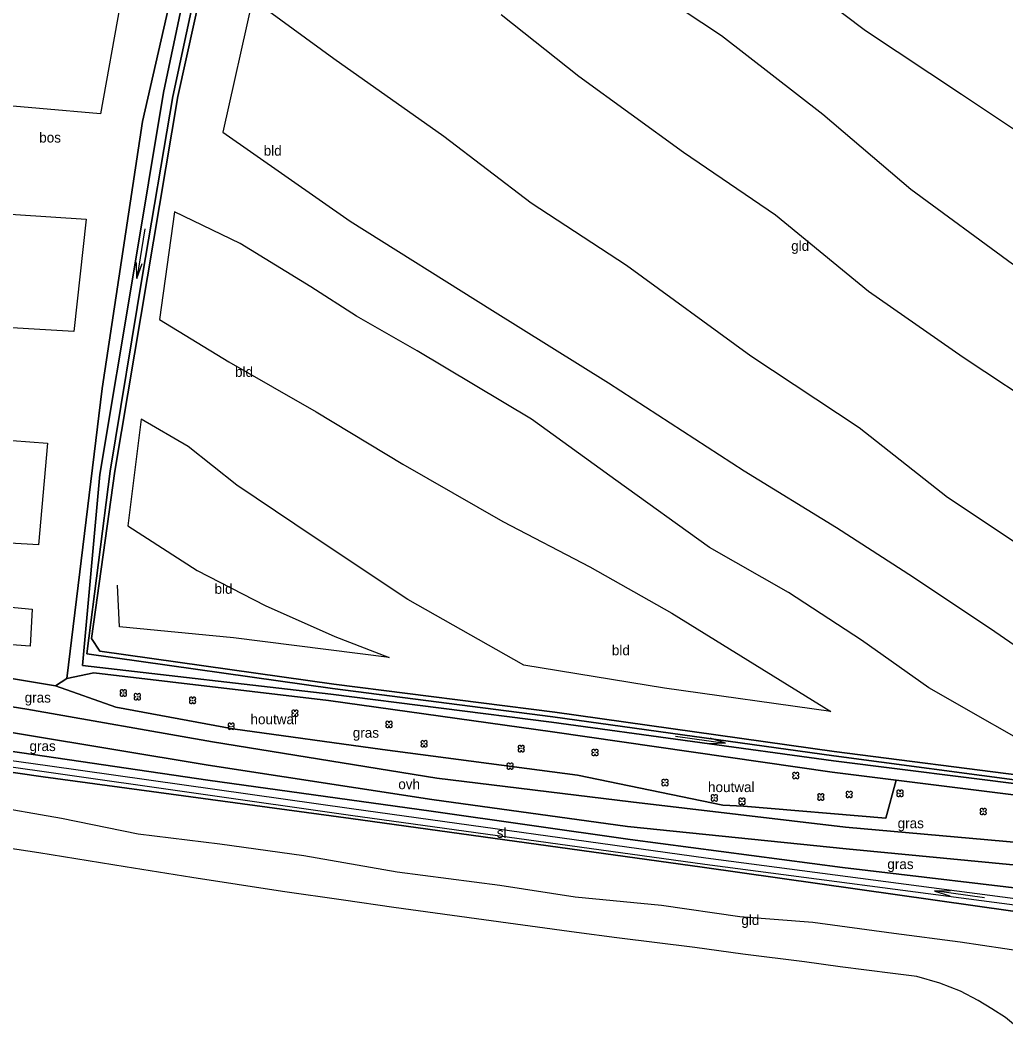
# Model space of a CAD drawing. Extents: x 154825 to 158680, y 370717 to 378075.
# Drawn here: x 155799.6 to 155897.3, y 376810.3 to 376911 of the extents above; entities that cross this region are included whole.
import ezdxf

# ---------------------------------------------------------------- set-up
doc = ezdxf.new("R2010")
doc.units = 0
for name, color, linetype in [('boom', 7, 'Continuous'), ('bos(vs)', 7, 'Continuous'), ('bouwland_akkerland(vs)', 7, 'Continuous'), ('cultuurscheiding', 7, 'Continuous'), ('grasland_productiegrasl(vs)', 7, 'Continuous'), ('grazige vegetatie(vs)', 7, 'Continuous'), ('hoogteverschillijn', 7, 'Continuous'), ('houtwal(vs)', 7, 'Continuous'), ('insteek sloot', 7, 'Continuous'), ('maaiveldlijn algemeen - onverhard', 7, 'Continuous'), ('onverhard(vs)', 7, 'Continuous'), ('Sloot bodem', 7, 'Continuous'), ('sloot(vs)', 7, 'Continuous'), ('stroomrichting  watergangen', 7, 'Continuous'), ('vlak_akkerland', 7, 'Continuous'), ('vlak_Bos', 7, 'Continuous'), ('vlak_Grasland', 7, 'Continuous'), ('vlak_Grazige_vegetatie', 7, 'Continuous')]:
    doc.layers.add(name, color=color, linetype=linetype)

msp = doc.modelspace()

# ---------------------------------------------------------------- linework, layer by layer
at = {"layer": 'boom'}
for centre in [(155809.83, 376844.31), (155811.22, 376843.93), (155816.7, 376843.58), (155826.83, 376842.3), (155820.51, 376841), (155836.16, 376841.19), (155839.63, 376839.27), (155849.26, 376838.79), (155856.58, 376838.4), (155848.16, 376837.06), (155876.48, 376836.12), (155863.52, 376835.43), (155868.4, 376833.91), (155871.14, 376833.57), (155878.96, 376834), (155881.77, 376834.25), (155886.81, 376834.36), (155895.06, 376832.55)]:
    msp.add_circle(centre, 0.006, dxfattribs=at)
for centre, start, end in [((155809.67, 376844.47), 357.075, 272.925), ((155809.99, 376844.47), 267.075, 182.925), ((155809.67, 376844.15), 87.075, 2.925), ((155809.99, 376844.15), 177.075, 92.925), ((155811.06, 376844.09), 357.075, 272.925), ((155811.06, 376843.77), 87.075, 2.925), ((155811.38, 376844.09), 267.075, 182.925), ((155811.38, 376843.77), 177.075, 92.925), ((155816.54, 376843.74), 357.075, 272.925), ((155816.54, 376843.42), 87.075, 2.925), ((155816.85, 376843.74), 267.075, 182.925), ((155816.85, 376843.42), 177.075, 92.925), ((155826.68, 376842.46), 357.075, 272.925), ((155826.99, 376842.46), 267.075, 182.925), ((155826.68, 376842.14), 87.075, 2.925), ((155826.99, 376842.14), 177.075, 92.925), ((155836, 376841.35), 357.075, 272.925), ((155836.32, 376841.35), 267.075, 182.925), ((155820.36, 376841.16), 357.075, 272.925), ((155820.36, 376840.85), 87.075, 2.925), ((155820.67, 376841.16), 267.075, 182.925), ((155820.67, 376840.85), 177.075, 92.925), ((155836, 376841.03), 87.075, 2.925), ((155836.32, 376841.03), 177.075, 92.925), ((155839.48, 376839.43), 357.075, 272.925), ((155839.79, 376839.43), 267.075, 182.925), ((155839.48, 376839.11), 87.075, 2.925), ((155839.79, 376839.11), 177.075, 92.925), ((155849.11, 376838.95), 357.075, 272.925), ((155849.11, 376838.63), 87.075, 2.925), ((155849.42, 376838.95), 267.075, 182.925), ((155849.42, 376838.63), 177.075, 92.925), ((155856.42, 376838.56), 357.075, 272.925), ((155856.73, 376838.56), 267.075, 182.925), ((155856.42, 376838.25), 87.075, 2.925), ((155856.73, 376838.25), 177.075, 92.925), ((155848, 376837.21), 357.075, 272.925), ((155848, 376836.9), 87.075, 2.925), ((155848.32, 376837.21), 267.075, 182.925), ((155848.32, 376836.9), 177.075, 92.925), ((155863.36, 376835.59), 357.075, 272.925), ((155863.67, 376835.59), 267.075, 182.925), ((155876.32, 376836.28), 357.075, 272.925), ((155876.32, 376835.96), 87.075, 2.925), ((155876.64, 376836.28), 267.075, 182.925), ((155876.64, 376835.96), 177.075, 92.925), ((155863.36, 376835.27), 87.075, 2.925), ((155863.67, 376835.27), 177.075, 92.925), ((155881.61, 376834.4), 357.075, 272.925), ((155881.93, 376834.4), 267.075, 182.925), ((155886.65, 376834.52), 357.075, 272.925), ((155886.97, 376834.52), 267.075, 182.925), ((155868.24, 376834.07), 357.075, 272.925), ((155868.24, 376833.75), 87.075, 2.925), ((155868.56, 376834.07), 267.075, 182.925), ((155868.56, 376833.75), 177.075, 92.925), ((155870.99, 376833.73), 357.075, 272.925), ((155870.99, 376833.41), 87.075, 2.925), ((155871.3, 376833.73), 267.075, 182.925), ((155871.3, 376833.41), 177.075, 92.925), ((155878.8, 376834.16), 357.075, 272.925), ((155878.8, 376833.84), 87.075, 2.925), ((155879.12, 376834.16), 267.075, 182.925), ((155879.12, 376833.84), 177.075, 92.925), ((155881.61, 376834.09), 87.075, 2.925), ((155881.93, 376834.09), 177.075, 92.925), ((155886.65, 376834.2), 87.075, 2.925), ((155886.97, 376834.2), 177.075, 92.925), ((155894.9, 376832.71), 357.075, 272.925), ((155894.9, 376832.4), 87.075, 2.925), ((155895.21, 376832.71), 267.075, 182.925), ((155895.21, 376832.4), 177.075, 92.925)]:
    msp.add_arc(centre, 0.158, start, end, dxfattribs=at)
at = {"layer": 'bos(vs)'}
msp.add_lwpolyline([(155707.98, 376936.31), (155709.06, 376926.66), (155710.19, 376916.09), (155711.3, 376903.83), (155707.93, 376894.26), (155707.32, 376891.22), (155709.05, 376884.55), (155711.14, 376878.22), (155715.14, 376871.74), (155721.77, 376865.05), (155731.05, 376858.48), (155738.77, 376855.49), (155749.59, 376852.93), (155762.49, 376851.8), (155803.11, 376845.02)], dxfattribs=at)
at = {"layer": 'cultuurscheiding'}
msp.add_lwpolyline([(155804.24, 376845.73), (155803.11, 376845.02)], dxfattribs=at)
at = {"layer": 'hoogteverschillijn'}
for points in [[(155874.66, 376916.61), (155883.38, 376909.98), (155892.9, 376903.67), (155900.14, 376898.84), (155908.78, 376893.81), (155916.88, 376889.16), (155924.11, 376884.74), (155933.83, 376879.1), (155929.3, 376866.27), (155918.02, 376873.64), (155908.49, 376879.84), (155897.95, 376886.83), (155887.87, 376894.23), (155879.15, 376901.66), (155869.11, 376909.47), (155861.42, 376914.58)], [(155901.98, 376856.72), (155891.51, 376863.7), (155882.76, 376870.61), (155872.03, 376877.7), (155859.69, 376886.7), (155850.25, 376892.86), (155841.61, 376899.48), (155830.7, 376907.17), (155822.64, 376913.11), (155819.68, 376899.92), (155832.3, 376891.07), (155846.42, 376882.22), (155857.91, 376875.04), (155871.35, 376866.32), (155880.5, 376860.73), (155888.13, 376855.79), (155896.2, 376850.4), (155902.14, 376846.3)], [(155809.5, 376912.57), (155807.56, 376901.73), (155795.44, 376902.79)], [(155847.28, 376911.58), (155854.99, 376905.45), (155865.34, 376897.94), (155874.47, 376891.7), (155883.67, 376884.14), (155893.08, 376877.6), (155901.55, 376871.98)], [(155792.6, 376892.19), (155806.16, 376891.28), (155804.92, 376880.15), (155795.39, 376880.7)], [(155902.52, 376837.48), (155889.68, 376844.82), (155882.99, 376849.55), (155875.74, 376854.28), (155867.94, 376858.73), (155858.63, 376865.41), (155850.29, 376871.45), (155838.96, 376878.23), (155832.94, 376881.67), (155828.41, 376884.57), (155821.42, 376888.86), (155814.89, 376892.02), (155813.41, 376881.34), (155820.29, 376877.15), (155828.94, 376872.18), (155837.53, 376866.99), (155847.44, 376861.3), (155856.07, 376856.81), (155864.19, 376852.23), (155879.95, 376842.48), (155863.48, 376844.78), (155849.52, 376847.08), (155838.02, 376853.57), (155828.74, 376859.74), (155821.08, 376864.91), (155816.24, 376868.75), (155811.58, 376871.45), (155810.27, 376860.87), (155817.16, 376856.45), (155823.89, 376852.98), (155830.8, 376849.9), (155836.17, 376847.82), (155820.74, 376849.77), (155809.46, 376850.87), (155809.25, 376854.98)], [(155793.52, 376869.72), (155802.32, 376869.07), (155801.42, 376858.99), (155789.45, 376859.68)], [(155793.41, 376853.32), (155800.78, 376852.61), (155800.6, 376848.94), (155785.32, 376850.07)], [(155796.09, 376833.21), (155803.71, 376831.9), (155811.31, 376830.35), (155819.39, 376829.36), (155827.73, 376828.18), (155836.97, 376826.58), (155847.15, 376825.24), (155854.61, 376824.11), (155863.16, 376823.27), (155870.92, 376822.14), (155878.16, 376821.57), (155886.21, 376820.5), (155892.77, 376819.62), (155901.63, 376818.3)], [(155899.45, 376810.33), (155897.26, 376812.15), (155895.92, 376813), (155894.54, 376813.82), (155892.79, 376814.76), (155890.75, 376815.55), (155888.48, 376816.21), (155886.08, 376816.49), (155880.88, 376817.16), (155877.34, 376817.64), (155871.24, 376818.42), (155866.47, 376819.06), (155858.73, 376820.04), (155854.73, 376820.55), (155844.83, 376821.9), (155836.65, 376823.05), (155831.64, 376823.75), (155825.59, 376824.62), (155816.62, 376826), (155810.02, 376827.08), (155801.47, 376828.46), (155795.3, 376829.39)]]:
    msp.add_lwpolyline(points, dxfattribs=at)
at = {"layer": 'houtwal(vs)'}
msp.add_lwpolyline([(155803.11, 376845.02), (155809.07, 376842.91), (155820.67, 376840.76), (155835.5, 376838.71), (155854.84, 376836.17), (155869.25, 376833.19), (155871.29, 376833.07), (155885.39, 376831.91), (155886.44, 376835.67)], dxfattribs=at)
at = {"layer": 'insteek sloot'}
for points in [[(155951.48, 376912.04), (155950.81, 376910.1), (155944.24, 376887.93), (155932.69, 376850.87), (155927.1, 376832.28), (155925.6, 376832.14), (155908.83, 376834.69), (155899.86, 376836), (155880.29, 376838.49), (155852.58, 376842.4), (155830.69, 376845.17), (155807.49, 376848.44), (155806.69, 376849.7), (155808.97, 376866.3), (155812.21, 376885.55), (155815.22, 376903.44), (155820.87, 376929.02), (155827.55, 376949.9), (155825.68, 376950.6)], [(155710.74, 376938.93), (155711.93, 376937.32), (155749.4, 376933.71), (155779.55, 376931.02), (155798.58, 376929.34), (155817.7, 376927.17), (155811.74, 376900.95), (155807.72, 376874.51), (155804.24, 376845.73)], [(155804.24, 376845.73), (155806.9, 376846.29), (155830.15, 376843.55), (155852.38, 376840.45), (155880.09, 376836.47), (155886.44, 376835.67), (155900.16, 376833.93), (155910.13, 376832.74), (155924.43, 376829.92), (155927.16, 376829.71), (155928.35, 376830.7), (155929.48, 376833.95), (155934.43, 376850.63), (155938.1, 376861.47), (155945.95, 376887.57), (155952.86, 376909.7), (155953.45, 376911.73), (155952.69, 376912.04), (155951.48, 376912.04)], [(155917.26, 376821.97), (155902.89, 376824.44), (155881.12, 376826.99), (155860.07, 376829.77), (155840.33, 376832.6), (155818.19, 376835.66), (155799.77, 376838.37), (155777.89, 376841.55)], [(155917.26, 376821.97), (155917.56, 376821.1), (155917.38, 376820.35), (155916.96, 376819.99), (155897.99, 376822.69), (155867.21, 376827.04), (155832.39, 376831.87), (155801.87, 376835.98), (155784.26, 376838.54)]]:
    msp.add_lwpolyline(points, dxfattribs=at)
at = {"layer": 'maaiveldlijn algemeen - onverhard'}
for points in [[(155761.97, 376849), (155778.08, 376846.25), (155800.28, 376842.69), (155818.67, 376839.48), (155840.9, 376835.86), (155860.13, 376833.5), (155881.4, 376830.99), (155903.31, 376829.04), (155916.93, 376827.42), (155923.18, 376826.59), (155927.44, 376827.44), (155929.98, 376827.65)], [(155927.76, 376819.58), (155925.74, 376822.59), (155921.05, 376823.98), (155916.67, 376825.04), (155903.18, 376826.77), (155881.48, 376828.86), (155859.8, 376831.07), (155840.39, 376833.74), (155818.23, 376837.16), (155799.73, 376840.22), (155778.26, 376843.76), (155761.03, 376845.99)]]:
    msp.add_lwpolyline(points, dxfattribs=at)
at = {"layer": 'Sloot bodem'}
for points in [[(155952.92, 376911.73), (155945.45, 376887.82), (155933.51, 376850.77), (155927.84, 376832.29), (155926.8, 376831.25), (155925.43, 376831.34), (155909.7, 376833.81), (155899.67, 376835.15), (155880.2, 376837.58), (155852.26, 376841.4), (155830.4, 376844.19), (155805.78, 376847.03), (155807.51, 376865.98), (155810.82, 376885.92), (155813.8, 376903.84), (155819.14, 376929.12)], [(155820.25, 376929.18), (155814.74, 376903.44), (155811.72, 376885.72), (155808.51, 376866.3), (155806.2, 376848.2), (155830.56, 376844.76), (155852.39, 376841.94), (155880.24, 376838.08), (155899.63, 376835.5), (155909.79, 376834.4), (155925.47, 376831.94), (155926.84, 376831.85), (155927.27, 376832.47), (155932.94, 376850.95), (155944.87, 376888), (155952.35, 376911.91)], [(155784.16, 376839.02), (155802.22, 376836.49), (155832.36, 376832.21), (155867.47, 376827.34), (155898.15, 376823.29), (155917.01, 376820.38), (155917.1, 376820.97), (155898.22, 376823.89), (155867.56, 376827.93), (155832.44, 376832.81), (155802.3, 376837.09), (155784.24, 376839.61)]]:
    msp.add_lwpolyline(points, dxfattribs=at)
at = {"layer": 'stroomrichting  watergangen'}
for p, q in [((155811.95, 376890.32), (155811.16, 376885.39)), ((155811.16, 376885.39), (155811.13, 376886.97)), ((155811.17, 376885.41), (155811.69, 376886.9)), ((155864.57, 376840.01), (155869.52, 376839.33)), ((155869.5, 376839.34), (155868, 376839.83)), ((155869.52, 376839.33), (155867.94, 376839.27)), ((155890.24, 376824.68), (155891.81, 376824.74)), ((155895.18, 376824), (155890.24, 376824.68)), ((155890.25, 376824.66), (155891.75, 376824.18))]:
    msp.add_line(p, q, dxfattribs=at)
at = {"layer": 'vlak_akkerland'}
msp.add_lwpolyline([(155951.48, 376912.04), (155950.81, 376910.1), (155944.24, 376887.93), (155932.69, 376850.87), (155927.1, 376832.28), (155925.6, 376832.14), (155908.83, 376834.69), (155899.86, 376836), (155880.29, 376838.49), (155852.58, 376842.4), (155830.69, 376845.17), (155807.49, 376848.44), (155806.69, 376849.7), (155808.97, 376866.3), (155812.21, 376885.55), (155815.22, 376903.44), (155820.87, 376929.02)], dxfattribs=at)
at = {"layer": 'vlak_Bos'}
msp.add_lwpolyline([(155804.24, 376845.73), (155803.11, 376845.02), (155762.49, 376851.8), (155749.59, 376852.93), (155738.77, 376855.49), (155731.05, 376858.48), (155721.77, 376865.05), (155715.14, 376871.74), (155711.14, 376878.22), (155709.05, 376884.55), (155707.32, 376891.22), (155707.93, 376894.26), (155711.3, 376903.83), (155710.19, 376916.09), (155709.06, 376926.66), (155707.98, 376936.31), (155710.74, 376938.93), (155711.93, 376937.32), (155749.4, 376933.71), (155779.55, 376931.02), (155798.58, 376929.34), (155817.7, 376927.17), (155811.74, 376900.95), (155807.72, 376874.51)], close=True, dxfattribs=at)
at = {"layer": 'vlak_Grasland'}
for points in [[(155784.26, 376838.54), (155801.87, 376835.98), (155832.39, 376831.87), (155867.21, 376827.04), (155897.99, 376822.69)], [(155899.45, 376810.33), (155897.26, 376812.15), (155895.92, 376813), (155894.54, 376813.82), (155892.79, 376814.76), (155890.75, 376815.55), (155888.48, 376816.21), (155886.08, 376816.49), (155880.88, 376817.16), (155877.34, 376817.64), (155871.24, 376818.42), (155866.47, 376819.06), (155858.73, 376820.04), (155854.73, 376820.55), (155844.83, 376821.9), (155836.65, 376823.05), (155831.64, 376823.75), (155825.59, 376824.62), (155816.62, 376826), (155810.02, 376827.08), (155801.47, 376828.46), (155795.3, 376829.39)]]:
    msp.add_lwpolyline(points, dxfattribs=at)
at = {"layer": 'vlak_Grazige_vegetatie'}
for points in [[(155819.14, 376929.12), (155813.8, 376903.84), (155810.82, 376885.92), (155807.51, 376865.98), (155805.78, 376847.03), (155830.4, 376844.19), (155852.26, 376841.4), (155880.2, 376837.58), (155899.67, 376835.15), (155909.7, 376833.81), (155925.43, 376831.34), (155926.8, 376831.25), (155927.84, 376832.29), (155933.51, 376850.77), (155945.45, 376887.82), (155952.92, 376911.73)], [(155952.35, 376911.91), (155944.87, 376888), (155932.94, 376850.95), (155927.27, 376832.47), (155926.84, 376831.85), (155925.47, 376831.94), (155909.79, 376834.4), (155899.63, 376835.5), (155880.24, 376838.08), (155852.39, 376841.94), (155830.56, 376844.76), (155806.2, 376848.2), (155808.51, 376866.3), (155811.72, 376885.72), (155814.74, 376903.44), (155820.25, 376929.18)], [(155820.87, 376929.02), (155815.22, 376903.44), (155812.21, 376885.55), (155808.97, 376866.3), (155806.69, 376849.7), (155807.49, 376848.44), (155830.69, 376845.17), (155852.58, 376842.4), (155880.29, 376838.49), (155899.86, 376836), (155908.83, 376834.69), (155925.6, 376832.14), (155927.1, 376832.28), (155932.69, 376850.87), (155944.24, 376887.93), (155950.81, 376910.1), (155951.48, 376912.04)], [(155953.45, 376911.73), (155952.86, 376909.7), (155945.95, 376887.57), (155938.1, 376861.47), (155934.43, 376850.63), (155929.48, 376833.95), (155928.35, 376830.7), (155927.16, 376829.71), (155924.43, 376829.92), (155910.13, 376832.74), (155900.16, 376833.93), (155886.44, 376835.67), (155880.09, 376836.47), (155852.38, 376840.45), (155830.15, 376843.55), (155806.9, 376846.29), (155804.24, 376845.73), (155807.72, 376874.51), (155811.74, 376900.95), (155817.7, 376927.17)], [(155956.7, 376912.48), (155956.22, 376910.97), (155955.91, 376910.5), (155952.86, 376900.4), (155947.66, 376884.05), (155941.73, 376864.55), (155933.19, 376837.22), (155929.98, 376827.65), (155927.44, 376827.44), (155923.18, 376826.59), (155916.93, 376827.42), (155903.31, 376829.04), (155881.4, 376830.99), (155860.13, 376833.5), (155840.9, 376835.86), (155818.67, 376839.48), (155800.28, 376842.69), (155778.08, 376846.25)], [(155762.49, 376851.8), (155803.11, 376845.02), (155809.07, 376842.91), (155820.67, 376840.76), (155835.5, 376838.71), (155854.84, 376836.17), (155869.25, 376833.19), (155871.29, 376833.07), (155885.39, 376831.91), (155886.44, 376835.67), (155900.16, 376833.93), (155910.13, 376832.74), (155924.43, 376829.92), (155927.16, 376829.71), (155928.35, 376830.7), (155929.48, 376833.95), (155934.43, 376850.63), (155938.1, 376861.47), (155945.95, 376887.57), (155952.86, 376909.7), (155953.45, 376911.73)], [(155778.26, 376843.76), (155799.73, 376840.22), (155818.23, 376837.16), (155840.39, 376833.74), (155859.8, 376831.07), (155881.48, 376828.86), (155903.18, 376826.77)], [(155902.89, 376824.44), (155881.12, 376826.99), (155860.07, 376829.77), (155840.33, 376832.6), (155818.19, 376835.66), (155799.77, 376838.37), (155777.89, 376841.55)], [(155777.89, 376841.55), (155799.77, 376838.37), (155818.19, 376835.66), (155840.33, 376832.6), (155860.07, 376829.77), (155881.12, 376826.99), (155902.89, 376824.44), (155917.26, 376821.97), (155917.56, 376821.1), (155917.38, 376820.35), (155916.96, 376819.99), (155897.99, 376822.69), (155867.21, 376827.04), (155832.39, 376831.87), (155801.87, 376835.98), (155784.26, 376838.54)], [(155784.16, 376839.02), (155802.22, 376836.49), (155832.36, 376832.21), (155867.47, 376827.34), (155898.15, 376823.29), (155917.01, 376820.38), (155917.1, 376820.97), (155898.22, 376823.89), (155867.56, 376827.93), (155832.44, 376832.81), (155802.3, 376837.09), (155784.24, 376839.61)]]:
    msp.add_lwpolyline(points, dxfattribs=at)
msp.add_lwpolyline([(155886.44, 376835.67), (155885.39, 376831.91), (155871.29, 376833.07), (155869.25, 376833.19), (155854.84, 376836.17), (155835.5, 376838.71), (155820.67, 376840.76), (155809.07, 376842.91), (155803.11, 376845.02), (155804.24, 376845.73), (155806.9, 376846.29), (155830.15, 376843.55), (155852.38, 376840.45), (155880.09, 376836.47)], close=True, dxfattribs=at)

# ---------------------------------------------------------------- texts
at = {"layer": 'bos(vs)'}
msp.add_text('bos', height=1, dxfattribs=at).set_placement((155801.49, 376898.88))
at = {"layer": 'bouwland_akkerland(vs)'}
for p in [(155823.74, 376897.58), (155820.9, 376875.65), (155818.87, 376854.14), (155858.25, 376848.05)]:
    msp.add_text('bld', height=1, dxfattribs=at).set_placement(p)
at = {"layer": 'grasland_productiegrasl(vs)'}
for p in [(155876.02, 376888.14), (155871.08, 376821.31)]:
    msp.add_text('gld', height=1, dxfattribs=at).set_placement(p)
at = {"layer": 'grazige vegetatie(vs)'}
for p in [(155800.05, 376843.36), (155832.57, 376839.87), (155800.53, 376838.55), (155886.57, 376830.9), (155885.55, 376826.85)]:
    msp.add_text('gras', height=1, dxfattribs=at).set_placement(p)
at = {"layer": 'houtwal(vs)'}
for p in [(155822.43, 376841.21), (155867.78, 376834.48)]:
    msp.add_text('houtwal', height=1, dxfattribs=at).set_placement(p)
at = {"layer": 'onverhard(vs)'}
msp.add_text('ovh', height=1, dxfattribs=at).set_placement((155837.08, 376834.77))
at = {"layer": 'sloot(vs)'}
msp.add_text('sl', height=1, dxfattribs=at).set_placement((155846.84, 376829.94))

doc.saveas('drawing.dxf')
